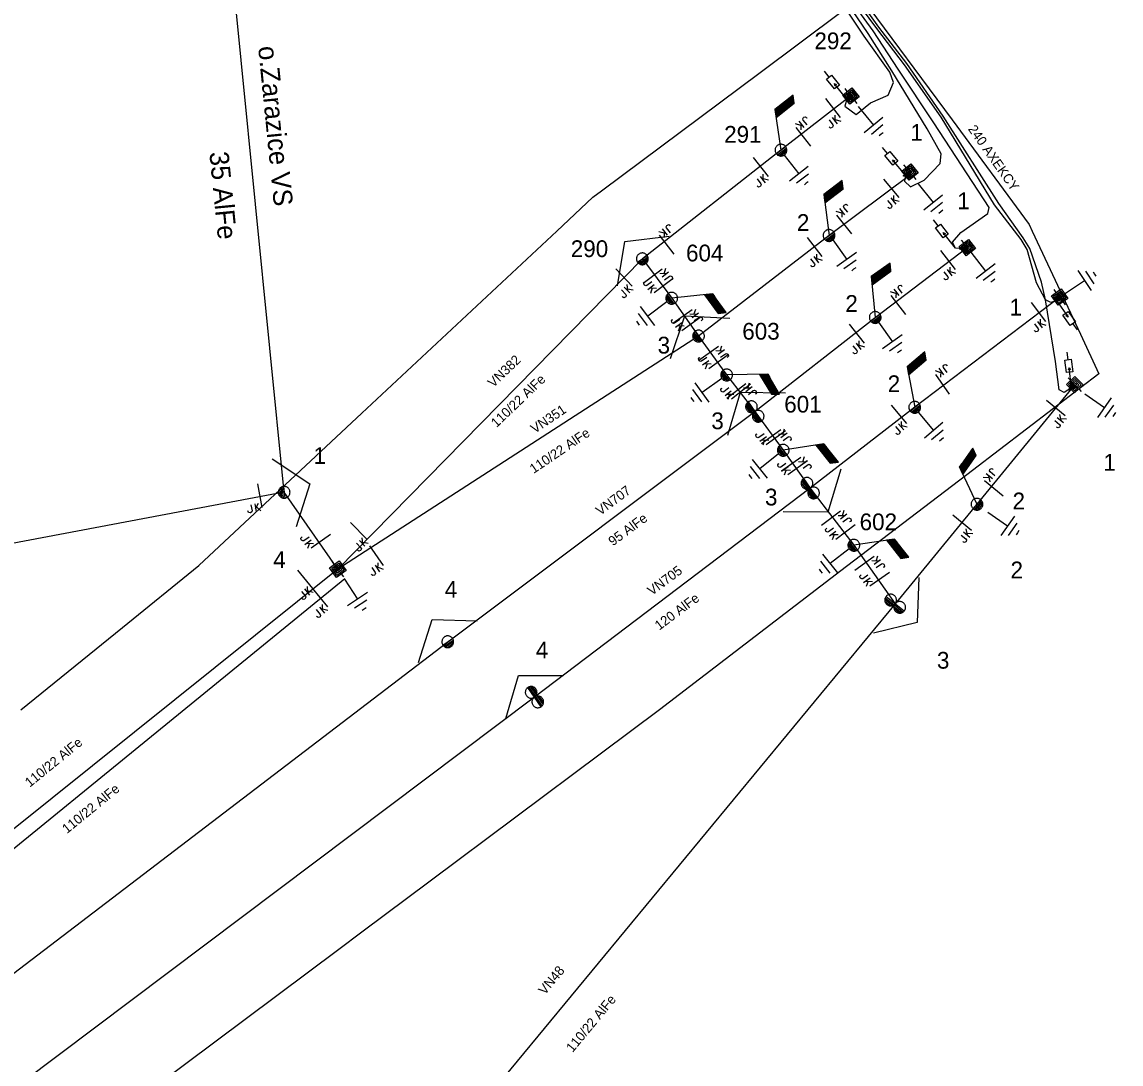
# Model space of a CAD drawing. Extents: x -545588 to -543214, y -1196037 to -1194452.
# Drawn here: x -545323 to -545208.3, y -1195024.5 to -1194915.7 of the extents above; entities that cross this region are included whole.
import ezdxf

# ---------------------------------------------------------------- set-up
doc = ezdxf.new("R2010")
doc.units = 0
for name, color, linetype in [('DOPLŇ_POPISY', 7, 'Continuous'), ('ELE_EON', 7, 'Continuous'), ('ELE_EON_POPIS', 7, 'Continuous'), ('Implicitní', 7, 'Continuous'), ('KONEC_VEDENÍ', 7, 'Continuous'), ('POL_ZNAČKA_PRACOVNÍ', 7, 'Continuous'), ('POL_ČÍSLO_PRACOVNÍ', 7, 'Continuous'), ('SDEL_EON', 7, 'Continuous'), ('SDEL_EON_POPIS', 7, 'Continuous'), ('TECH_OCHR_PÁSMO_HRAN', 7, 'Continuous'), ('Vrstva 18', 7, 'Continuous'), ('Vrstva 19', 7, 'Continuous'), ('Vrstva 35', 7, 'Continuous'), ('Vrstva 52', 7, 'Continuous'), ('Vrstva 53', 7, 'Continuous'), ('Vrstva 54', 7, 'Continuous'), ('ZP_EON', 7, 'Continuous'), ('ZP_EON_POPIS', 7, 'Continuous')]:
    doc.layers.add(name, color=color, linetype=linetype)

# ---------------------------------------------------------------- blocks, each defined once
blk = doc.blocks.new('VN840')
at = {"layer": 'POL_ZNAČKA_PRACOVNÍ'}
for points in [[(-0.01, 1.41), (-0.01, -1.09)], [(-1.51, -1.24), (-1.51, -1.15)], [(-1.09, -0.59), (-1.09, -1.24)], [(-0.68, -0.59), (-0.68, -1.42)], [(-0.68, -1.11), (-0.27, -0.59)], [(-0.54, -0.94), (-0.2, -1.42)], [(-1.48, -1.35), (-1.51, -1.24)], [(-1.33, -1.42), (-1.48, -1.35)], [(-1.27, -1.42), (-1.33, -1.42)], [(-1.13, -1.35), (-1.27, -1.42)], [(-1.09, -1.24), (-1.13, -1.35)]]:
    blk.add_lwpolyline(points, dxfattribs=at)
blk = doc.blocks.new('VN860')
at = {"layer": 'POL_ZNAČKA_PRACOVNÍ'}
for points in [[(-3.74, 0), (0.01, 2.82)], [(0.01, 2.82), (3.76, 0)]]:
    blk.add_lwpolyline(points, dxfattribs=at)
blk = doc.blocks.new('VN440')
at = {"layer": 'ELE_EON_POPIS'}
for points in [[(1.22, 0), (1.21, 0.13), (1.19, 0.25), (1.16, 0.38), (1.11, 0.5), (1.05, 0.61), (0.98, 0.72), (0.9, 0.82), (0.81, 0.91), (0.71, 0.99), (0.6, 1.06), (0.49, 1.12), (0.37, 1.16), (0.25, 1.2), (0.12, 1.22), (-0.01, 1.22), (-0.14, 1.22), (-0.26, 1.2), (-0.39, 1.16), (-0.51, 1.12), (-0.62, 1.06), (-0.73, 0.99), (-0.83, 0.91), (-0.92, 0.82), (-1, 0.72), (-1.07, 0.61), (-1.13, 0.5), (-1.18, 0.38), (-1.21, 0.25), (-1.23, 0.13), (-1.24, 0), (-1.23, -0.13), (-1.21, -0.26), (-1.18, -0.38), (-1.13, -0.5), (-1.07, -0.62), (-1, -0.73), (-0.92, -0.83), (-0.83, -0.92), (-0.73, -1), (-0.62, -1.07), (-0.51, -1.13), (-0.39, -1.17), (-0.26, -1.2), (-0.14, -1.23), (-0.01, -1.23), (0.12, -1.23), (0.25, -1.2), (0.37, -1.17), (0.49, -1.13), (0.6, -1.07), (0.71, -1), (0.81, -0.92), (0.9, -0.83), (0.98, -0.73), (1.05, -0.62), (1.11, -0.5), (1.16, -0.38), (1.19, -0.26), (1.21, -0.13), (1.22, 0)], [(-1.24, 0), (1.22, 0)], [(-1.18, -0.34), (1.1, -0.34)], [(-1.01, -0.63), (0.97, -0.63)], [(-0.74, -0.92), (0.68, -0.92)]]:
    blk.add_lwpolyline(points, dxfattribs=at)
blk = doc.blocks.new('VN890')
at = {"layer": 'SDEL_EON_POPIS'}
for points in [[(-0.41, 0.41), (0.41, 0)], [(-0.41, -0.41), (-0.41, 0.41)], [(0.41, 0), (-0.41, -0.41)], [(-0.34, 0.31), (0.27, 0), (-0.34, -0.3), (-0.34, 0.31)], [(-0.26, 0.2), (0.1, 0), (-0.26, -0.18), (-0.26, 0.2)], [(-0.19, 0.09), (-0.04, 0), (-0.19, -0.08), (-0.19, 0.09)], [(-0.16, -0.01), (-0.16, 0.03), (-0.13, 0.01), (-0.16, -0.01)]]:
    blk.add_lwpolyline(points, dxfattribs=at)
blk = doc.blocks.new('VN820')
at = {"layer": 'DOPLŇ_POPISY'}
for points in [[(0, 0), (0, -2.1)], [(-0.32, -1.63), (0.34, -1.63)], [(-0.32, -2.95), (-0.32, -1.63)], [(0, -2.1), (-0.12, -1.86)], [(0, -2.1), (0.12, -1.86)], [(0.34, -1.63), (0.34, -2.95)], [(0.34, -2.95), (-0.32, -2.95)], [(0, -2.95), (0, -3.75)]]:
    blk.add_lwpolyline(points, dxfattribs=at)
blk = doc.blocks.new('VN810')
at = {"layer": 'POL_ZNAČKA_PRACOVNÍ'}
for points in [[(0, -1.25), (0, -3.75)], [(1.25, -3.75), (-1.25, -3.75)], [(0.77, -4.37), (-0.8, -4.37)], [(0, -5), (-0.25, -5)], [(0.27, -5), (0, -5)]]:
    blk.add_lwpolyline(points, dxfattribs=at)
blk = doc.blocks.new('VN450')
at = {"layer": 'ELE_EON_POPIS'}
for points in [[(0, 0), (-0.01, 0.13), (-0.03, 0.25), (-0.06, 0.38), (-0.11, 0.5), (-0.16, 0.61), (-0.23, 0.72), (-0.31, 0.82), (-0.4, 0.91), (-0.5, 0.99), (-0.61, 1.06), (-0.72, 1.11), (-0.84, 1.16), (-0.97, 1.19), (-1.09, 1.21), (-1.22, 1.22), (-1.35, 1.21), (-1.47, 1.19), (-1.59, 1.16), (-1.71, 1.11), (-1.83, 1.06), (-1.93, 0.99), (-2.03, 0.91), (-2.12, 0.82), (-2.2, 0.72), (-2.27, 0.61), (-2.33, 0.5), (-2.38, 0.38), (-2.41, 0.25), (-2.43, 0.13), (-2.44, 0), (-2.43, -0.13), (-2.41, -0.25), (-2.38, -0.38), (-2.33, -0.5), (-2.27, -0.61), (-2.2, -0.72), (-2.12, -0.82), (-2.03, -0.91), (-1.93, -0.99), (-1.83, -1.06), (-1.71, -1.11), (-1.59, -1.16), (-1.47, -1.19), (-1.35, -1.21), (-1.22, -1.22), (-1.09, -1.21), (-0.97, -1.19), (-0.84, -1.16), (-0.72, -1.11), (-0.61, -1.06), (-0.5, -0.99), (-0.4, -0.91), (-0.31, -0.82), (-0.23, -0.72), (-0.16, -0.61), (-0.11, -0.5), (-0.06, -0.38), (-0.03, -0.25), (-0.01, -0.13), (0, 0)], [(-2.44, 0), (2.44, 0)], [(2.44, 0), (2.43, 0.13), (2.41, 0.25), (2.38, 0.38), (2.33, 0.5), (2.27, 0.61), (2.2, 0.72), (2.12, 0.82), (2.03, 0.91), (1.94, 0.99), (1.83, 1.06), (1.71, 1.11), (1.6, 1.16), (1.47, 1.19), (1.35, 1.21), (1.22, 1.22), (1.09, 1.21), (0.97, 1.19), (0.84, 1.16), (0.72, 1.11), (0.61, 1.06), (0.5, 0.99), (0.4, 0.91), (0.31, 0.82), (0.23, 0.72), (0.16, 0.61), (0.11, 0.5), (0.06, 0.38), (0.03, 0.25), (0.01, 0.13), (0, 0), (0.01, -0.13), (0.03, -0.25), (0.06, -0.38), (0.11, -0.5), (0.16, -0.61), (0.23, -0.72), (0.31, -0.82), (0.4, -0.91), (0.5, -0.99), (0.61, -1.06), (0.72, -1.11), (0.84, -1.16), (0.97, -1.19), (1.09, -1.21), (1.22, -1.22), (1.35, -1.21), (1.47, -1.19), (1.6, -1.16), (1.71, -1.11), (1.83, -1.06), (1.94, -0.99), (2.03, -0.91), (2.12, -0.82), (2.2, -0.72), (2.27, -0.61), (2.33, -0.5), (2.38, -0.38), (2.41, -0.25), (2.43, -0.13), (2.44, 0)], [(-2.4, -0.31), (-0.04, -0.31)], [(-2.26, -0.61), (-0.17, -0.61)], [(-2.01, -0.92), (-0.42, -0.92)], [(0.04, -0.31), (2.4, -0.31)], [(0.17, -0.61), (2.27, -0.61)], [(0.42, -0.92), (2.02, -0.92)]]:
    blk.add_lwpolyline(points, dxfattribs=at)
blk = doc.blocks.new('VN001')
at = {"layer": 'Implicitní'}
for p, q in [((1.99, 3.48), (4.4, 3.48)), ((2.02, 3.53), (4.43, 3.53)), ((2.05, 3.58), (4.46, 3.58)), ((2.07, 3.63), (4.49, 3.63)), ((2.1, 3.68), (4.52, 3.68)), ((2.13, 3.73), (2.54, 3.73)), ((1.73, 3.03), (4.14, 3.03)), ((1.76, 3.08), (4.17, 3.08)), ((1.79, 3.13), (4.2, 3.13)), ((1.82, 3.18), (4.23, 3.18)), ((1.85, 3.23), (4.26, 3.23)), ((1.87, 3.28), (4.29, 3.28)), ((1.9, 3.33), (4.32, 3.33)), ((1.93, 3.38), (4.35, 3.38)), ((1.96, 3.43), (4.37, 3.43))]:
    blk.add_line(p, q, dxfattribs=at)
blk.add_lwpolyline([(2.13, 3.73), (0, 0)], dxfattribs=at)
blk.add_lwpolyline([(4.55, 3.73), (2.13, 3.73), (1.7, 2.98), (4.12, 2.99)], close=True, dxfattribs=at)
blk = doc.blocks.new('VN470')
at = {"layer": 'ELE_EON_POPIS'}
for points in [[(-1.23, 1.22), (1.23, 1.22)], [(-1.23, -1.23), (-1.23, 1.22)], [(-0.92, 0.9), (0.92, 0.9)], [(-0.92, -0.95), (-0.92, 0.9)], [(-0.61, 0.61), (0.61, 0.61)], [(-0.61, -0.62), (-0.61, 0.61)], [(-0.31, -0.27), (-0.31, 0.34)], [(-0.31, 0.34), (0.31, 0.34)], [(0, 1.22), (0, 1.97)], [(0.31, 0.34), (0.31, -0.27)], [(0.61, 0.61), (0.61, -0.62)], [(0.92, 0.9), (0.92, -0.95)], [(1.23, 1.22), (1.23, -1.23)], [(1.23, -1.23), (-1.23, -1.23)], [(0.92, -0.95), (-0.92, -0.95)], [(0.61, -0.62), (-0.61, -0.62)], [(0.31, -0.27), (-0.31, -0.27)], [(0, -1.23), (0, -1.98)]]:
    blk.add_lwpolyline(points, dxfattribs=at)

msp = doc.modelspace()

# ---------------------------------------------------------------- linework, layer by layer
at = {"layer": 'ELE_EON'}
for points in [[(-545236.46, -1194923.4), (-545243.76, -1194929.05)], [(-545243.76, -1194929.05), (-545258.23, -1194940.4)], [(-545230.22, -1194931.6), (-545238.74, -1194937.96)], [(-545238.74, -1194937.96), (-545252.36, -1194948.47)], [(-545233.92, -1194946.52), (-545224.31, -1194939.23)], [(-545258.23, -1194940.4), (-545290.02, -1194972.8)], [(-545214.67, -1194944.4), (-545229.8, -1194955.9)], [(-545246.49, -1194956.34), (-545233.92, -1194946.52)], [(-545252.36, -1194948.47), (-545290.02, -1194972.8)], [(-545213.1, -1194953.54), (-545223.3, -1194966.03)], [(-545395.75, -1195077.92), (-545332.4, -1195021.48), (-545278.54, -1194980.38), (-545246.49, -1194956.34)], [(-545229.8, -1194955.9), (-545240.7, -1194964.34)], [(-545240.7, -1194964.34), (-545269.49, -1194986.16), (-545326.84, -1195029.29), (-545358.05, -1195052.83)], [(-545223.3, -1194966.03), (-545231.84, -1194976.41)], [(-545290.02, -1194972.8), (-545405.11, -1195065.07), (-545495.54, -1195139.14), (-545571.44, -1195160.65)], [(-545289.27, -1194973.82), (-545403.67, -1195067.08), (-545494.32, -1195141.28), (-545571.32, -1195163.18)], [(-545231.84, -1194976.41), (-545288.22, -1195044.64), (-545343.3, -1195111.41), (-545397.6, -1195177.04), (-545441.95, -1195249.1), (-545485.78, -1195319.69), (-545525.23, -1195383.69), (-545557.58, -1195435.71)]]:
    msp.add_lwpolyline(points, dxfattribs=at)
at = {"layer": 'Vrstva 35'}
for points in [[(-545235.38, -1194913.06), (-545225.9, -1194925.9), (-545217.85, -1194936.81), (-545217.53, -1194937.5), (-545215.93, -1194940.93), (-545212.5, -1194948.28), (-545210.58, -1194952.4), (-545212.5, -1194953.87), (-545223.78, -1194962.5), (-545237.5, -1194972.99), (-545256.45, -1194987.5), (-545262.5, -1194992.01), (-545280.38, -1195005.38), (-545287.5, -1195010.7), (-545289.91, -1195012.5), (-545312.5, -1195029.39)], [(-545323.09, -1194987.5), (-545312.5, -1194978.9), (-545304.54, -1194972.43), (-545293.92, -1194962.5), (-545287.5, -1194956.5), (-545267.17, -1194937.5), (-545263.39, -1194933.97), (-545262.5, -1194933.31), (-545245.95, -1194920.95), (-545237.5, -1194914.64)]]:
    msp.add_lwpolyline(points, dxfattribs=at)
at = {"layer": 'Vrstva 52'}
for points in [[(-545295.62, -1194964.78), (-545301.62, -1194904.6), (-545301.79, -1194902.92), (-545302.62, -1194901.45), (-545318.54, -1194873.42)], [(-545258.23, -1194940.4), (-545255.17, -1194944.52)], [(-545255.17, -1194944.52), (-545252.36, -1194948.47)], [(-545252.36, -1194948.47), (-545249.44, -1194952.53)], [(-545249.44, -1194952.53), (-545246.49, -1194956.34)], [(-545246.49, -1194956.34), (-545243.52, -1194960.39)], [(-545243.52, -1194960.39), (-545240.53, -1194964.58)], [(-545295.62, -1194964.78), (-545381.37, -1194980.94), (-545453.74, -1194986.07), (-545493.42, -1194989.16)], [(-545290.02, -1194972.8), (-545295.62, -1194964.78)], [(-545240.53, -1194964.58), (-545236.15, -1194970.31)], [(-545236.15, -1194970.31), (-545231.84, -1194976.41)]]:
    msp.add_lwpolyline(points, dxfattribs=at)
at = {"layer": 'ZP_EON'}
for points in [[(-545236.49, -1194923.55), (-545236.72, -1194923.58), (-545236.89, -1194923.73), (-545237.09, -1194924.48), (-545235.92, -1194925.33), (-545234.43, -1194924.11), (-545232.58, -1194923.3), (-545232.02, -1194922.01), (-545232.39, -1194920.91), (-545235.07, -1194917.17), (-545239.41, -1194910.6)], [(-545230.31, -1194931.31), (-545230.78, -1194931.68), (-545230.78, -1194931.68), (-545230.86, -1194932.28), (-545230.25, -1194932.87), (-545228.8, -1194932.18), (-545227.16, -1194930.44), (-545227.04, -1194929.44), (-545228.49, -1194926.82), (-545232.2, -1194920.78), (-545234.65, -1194916.87), (-545239.05, -1194910.4)], [(-545224.18, -1194939.38), (-545224.73, -1194939.37), (-545225.56, -1194939.3), (-545225.86, -1194938.67), (-545224.97, -1194937.65), (-545222.16, -1194935.67), (-545222.02, -1194935.04), (-545227.82, -1194926.2), (-545231.53, -1194920.6), (-545234.13, -1194916.6), (-545238.74, -1194910.26)], [(-545214.51, -1194944.61), (-545214.64, -1194944.43), (-545214.85, -1194944.63), (-545215, -1194944.76), (-545215.59, -1194944.96), (-545216.14, -1194944.67), (-545217.09, -1194942.9), (-545218.06, -1194939.43), (-545218.69, -1194938.4), (-545221.46, -1194934.77), (-545227.03, -1194925.62), (-545230.86, -1194920.16), (-545233.75, -1194916.35), (-545238.35, -1194910.11)], [(-545213.08, -1194953.79), (-545213.42, -1194953.86), (-545214.2, -1194954.37), (-545214.73, -1194954.07), (-545215.11, -1194951.12), (-545216.14, -1194944.67), (-545216.55, -1194942.85), (-545217.78, -1194939.34), (-545218.48, -1194938.21), (-545221.01, -1194934.62), (-545226.84, -1194925.51), (-545230.61, -1194920), (-545233.55, -1194916.21), (-545237.86, -1194910.11)]]:
    msp.add_lwpolyline(points, dxfattribs=at)

# ---------------------------------------------------------------- block references
at = {"layer": 'DOPLŇ_POPISY'}
for name, p, xscale, yscale, rotation in [('VN470', (-545236.46, -1194923.4), 0.5000000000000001, 0.5, 38.57166112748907), ('VN440', (-545243.76, -1194929.05), 0.5, 0.5, 38.18600550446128), ('VN470', (-545230.3, -1194931.34), 0.5, 0.5000000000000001, 39.025683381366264), ('VN440', (-545238.74, -1194937.96), 0.5, 0.49999999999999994, 34.95319163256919), ('VN470', (-545224.31, -1194939.23), 0.5, 0.5000000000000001, 37.661386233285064), ('VN440', (-545258.23, -1194940.4), 0.5, 0.5, 35.95226383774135), ('VN440', (-545255.16, -1194944.52), 0.5, 0.5, -53.39277781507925), ('VN470', (-545214.67, -1194944.4), 0.5, 0.5, 35.09740273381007), ('VN440', (-545233.92, -1194946.52), 0.5, 0.5000000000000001, 35.223016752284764), ('VN440', (-545252.36, -1194948.47), 0.5, 0.5, -54.047736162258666), ('VN440', (-545249.43, -1194952.53), 0.5, 0.5, -54.273602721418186), ('VN470', (-545213.1, -1194953.54), 0.5, 0.49999999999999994, 43.663602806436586), ('VN450', (-545246.49, -1194956.34), 0.5000000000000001, 0.4999999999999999, -54.77698328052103), ('VN440', (-545229.8, -1194955.9), 0.5, 0.5, 40.44745010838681), ('VN440', (-545243.52, -1194960.39), 0.5, 0.49999999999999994, -51.362411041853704), ('VN450', (-545240.7, -1194964.34), 0.5000000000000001, 0.5, -55.28859164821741), ('VN440', (-545295.62, -1194964.78), 0.5, 0.5, -84.30825828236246), ('VN440', (-545223.3, -1194966.02), 0.5, 0.5, 50.71019441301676), ('VN440', (-545236.15, -1194970.31), 0.5, 0.5, -54.644949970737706), ('VN470', (-545290.02, -1194972.8), 0.5, 0.5, 35.95226383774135), ('VN450', (-545231.84, -1194976.41), 0.5, 0.4999999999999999, -38.48263617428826), ('VN440', (-545278.54, -1194980.38), 0.49999999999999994, 0.5000000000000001, 35.22301664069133), ('VN450', (-545269.49, -1194986.16), 0.49999999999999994, 0.5, 124.71140827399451)]:
    msp.add_blockref(name, p, dxfattribs=dict(at, xscale=xscale, yscale=yscale, rotation=rotation))
at = {"layer": 'POL_ZNAČKA_PRACOVNÍ'}
for p, rotation in [((-545236.49, -1194923.55), 39.57557080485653), ((-545244.21, -1194928.59), 38.18696673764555), ((-545230.22, -1194931.6), 38.759191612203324), ((-545239.06, -1194937.41), 35.223016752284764), ((-545224.7, -1194938.73), 37.66631396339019), ((-545215.21, -1194944.74), 123.37775649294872), ((-545254.66, -1194944.14), -53.40005286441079), ((-545234.29, -1194946), 35.223016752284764), ((-545248.93, -1194952.16), -54.27577217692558), ((-545213.08, -1194953.79), 55.019999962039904), ((-545230.26, -1194955.46), 40.4480305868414), ((-545243.03, -1194959.99), -51.35691383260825), ((-545223.18, -1194966.13), 55.0153639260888), ((-545235.68, -1194969.89), -51.52944450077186), ((-545290.02, -1194972.8), 33.3588583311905)]:
    msp.add_blockref('VN810', p, dxfattribs=dict(at, rotation=rotation))
at = {"layer": 'POL_ČÍSLO_PRACOVNÍ'}
for p, rotation in [((-545236.89, -1194923.73), -141.52061114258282), ((-545230.78, -1194931.68), -140.71454174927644), ((-545225.56, -1194939.3), -142.37886389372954), ((-545215, -1194944.76), 35.09724162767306), ((-545213.42, -1194953.86), -172.82982508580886)]:
    msp.add_blockref('VN820', p, dxfattribs=dict(at, rotation=rotation))
at = {"layer": 'TECH_OCHR_PÁSMO_HRAN'}
for p, rotation in [((-545243.76, -1194929.05), 38.18679450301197), ((-545238.74, -1194937.96), 37.17218889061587), ((-545233.92, -1194946.52), 35.223016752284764), ((-545255.17, -1194944.52), -54.047736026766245), ((-545229.8, -1194955.9), 40.44745010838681), ((-545249.44, -1194952.53), -59.175191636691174), ((-545243.52, -1194960.39), -51.362411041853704), ((-545223.3, -1194966.03), 55.0153638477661), ((-545236.15, -1194970.31), -51.52944450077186)]:
    msp.add_blockref('VN001', p, dxfattribs=dict(at, rotation=rotation))
at = {"layer": 'Vrstva 18'}
for name, p, rotation in [('VN840', (-545238.24, -1194924.77), 37.809900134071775), ('VN840', (-545241.52, -1194927.56), -141.42955829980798), ('VN840', (-545245.77, -1194930.93), 38.18633062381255), ('VN840', (-545232.15, -1194933.16), 39.020663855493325), ('VN840', (-545237.25, -1194936.69), -140.97279439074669), ('VN860', (-545258.13, -1194940.65), 43.75872502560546), ('VN840', (-545255.79, -1194938.81), -141.81291385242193), ('VN840', (-545240.15, -1194939.28), 37.16967780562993), ('VN840', (-545226.25, -1194940.64), 37.484938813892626), ('VN840', (-545260.03, -1194942.47), 43.759150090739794), ('VN840', (-545257.04, -1194942.09), 127.11686113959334), ('VN840', (-545256.12, -1194943.31), -52.88313888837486), ('VN840', (-545231.61, -1194945.11), -142.3361888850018), ('VN860', (-545252.21, -1194948.71), 34.11712501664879), ('VN840', (-545253.22, -1194947.29), -54.55751941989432), ('VN840', (-545253.92, -1194946.31), 125.44248060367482), ('VN840', (-545216.8, -1194946.07), 37.15255827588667), ('VN840', (-545235.76, -1194948.34), 38.29414440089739), ('VN840', (-545250.4, -1194951.25), -54.52896109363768), ('VN840', (-545251.19, -1194950.14), 125.47103896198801), ('VN860', (-545246.31, -1194956.61), 36.40879723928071), ('VN840', (-545248.06, -1194954.38), -51.92876399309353), ('VN840', (-545226.98, -1194953.38), -144.89947772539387), ('VN840', (-545248.3, -1194954.07), 128.07123606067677), ('VN840', (-545231.35, -1194956.75), 40.44653339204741), ('VN840', (-545214.94, -1194956.06), 50.7004805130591), ('VN840', (-545244.41, -1194959.19), -53.56914167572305), ('VN840', (-545244.66, -1194958.85), 126.430858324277), ('VN860', (-545295.62, -1194964.82), -70.65378887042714), ('VN840', (-545242.14, -1194962.33), -54.48819997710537), ('VN840', (-545242.57, -1194961.72), 125.51179994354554), ('VN860', (-545240.53, -1194964.58), -143.3872638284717), ('VN840', (-545221.67, -1194964.28), -129.2995194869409), ('VN840', (-545298.13, -1194965.29), 10.64668321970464), ('VN840', (-545238.42, -1194967.36), 127.18888063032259), ('VN840', (-545237.15, -1194969.04), -52.811119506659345), ('VN840', (-545224.72, -1194968.02), 50.71059436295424), ('VN840', (-545291.91, -1194970), -54.584030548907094), ('VN840', (-545287.69, -1194968.92), 44.07588337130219), ('VN840', (-545285.91, -1194971.51), 34.4793945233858), ('VN840', (-545234.92, -1194972.07), 125.29263057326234), ('VN840', (-545293.33, -1194973.98), 39.18124444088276), ('VN840', (-545233.58, -1194973.97), -54.70736942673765), ('VN860', (-545231.73, -1194976.58), -129.28824718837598), ('VN840', (-545291.79, -1194975.87), 39.189741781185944), ('VN860', (-545278.54, -1194980.38), 35.22301664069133), ('VN860', (-545269.49, -1194986.16), 36.89043607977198)]:
    msp.add_blockref(name, p, dxfattribs=dict(at, rotation=rotation))
at = {"layer": 'Vrstva 19'}
for p, rotation in [((-545236.72, -1194923.58), -141.34019170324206), ((-545230.61, -1194931.66), -171.49811939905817), ((-545224.73, -1194939.37), 178.8509611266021), ((-545214.85, -1194944.63), -137.48955276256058), ((-545213.42, -1194953.86), -134.2361027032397)]:
    msp.add_blockref('VN890', p, dxfattribs=dict(at, rotation=rotation))

# ---------------------------------------------------------------- texts
at = {"layer": 'ELE_EON_POPIS'}
for s, rotation, p in [('110/22 AlFe', 43.759, (-545273.46, -1194958.08)), ('110/22 AlFe', 34.117, (-545269.57, -1194962.86)), ('95 AlFe', 36.409, (-545261.31, -1194970.43)), ('120 AlFe', 36.692, (-545256.47, -1194979.23)), ('110/22 AlFe', 39.181, (-545322.17, -1194995.62)), ('110/22 AlFe', 39.19, (-545318.29, -1195000.46)), ('110/22 AlFe', 50.365, (-545265.51, -1195023.32))]:
    msp.add_text(s, height=1, rotation=rotation, dxfattribs=at).set_placement(p)
at = {"layer": 'KONEC_VEDENÍ'}
for s, p in [('2', (-545219.59, -1194966.56)), ('602', (-545235.55, -1194968.74))]:
    msp.add_text(s, height=1.75, dxfattribs=at).set_placement(p)
at = {"layer": 'POL_ZNAČKA_PRACOVNÍ'}
for s, p in [('292', (-545240.27, -1194918.52)), ('291', (-545249.69, -1194928.28)), ('1', (-545230.25, -1194928.08)), ('1', (-545225.36, -1194935.22)), ('2', (-545242.1, -1194937.49)), ('290', (-545265.7, -1194940.22)), ('604', (-545253.67, -1194940.67)), ('2', (-545237.04, -1194945.94)), ('1', (-545219.91, -1194946.32)), ('603', (-545247.8, -1194948.84)), ('3', (-545256.64, -1194950.29)), ('2', (-545232.62, -1194954.32)), ('601', (-545243.42, -1194956.45)), ('3', (-545251.03, -1194958.19)), ('1', (-545292.56, -1194961.82)), ('1', (-545210.11, -1194962.53)), ('3', (-545245.43, -1194966.15)), ('4', (-545296.76, -1194972.68)), ('2', (-545219.8, -1194973.76)), ('4', (-545278.85, -1194975.78)), ('4', (-545269.35, -1194982.11)), ('3', (-545227.48, -1194983.19))]:
    msp.add_text(s, height=1.75, dxfattribs=at).set_placement(p)
at = {"layer": 'SDEL_EON'}
for s, rotation, p in [('VN382', 43.759, (-545273.79, -1194953.9)), ('VN351', 34.117, (-545269.46, -1194958.68)), ('VN707', 36.409, (-545262.63, -1194967.24)), ('VN705', 36.692, (-545257.24, -1194975.6)), ('VN48', 50.365, (-545268.41, -1195017.32))]:
    msp.add_text(s, height=1, rotation=rotation, dxfattribs=at).set_placement(p)
at = {"layer": 'Vrstva 53'}
msp.add_text('35 AlFe', height=2, rotation=275.692, dxfattribs=at).set_placement((-545303.43, -1194929.29))
at = {"layer": 'Vrstva 54'}
msp.add_text('o.Zarazice VS', height=2, rotation=275.692, dxfattribs=at).set_placement((-545298.34, -1194918.27))
at = {"layer": 'ZP_EON_POPIS'}
msp.add_text('240 AXEKCY', height=1, rotation=305.174, dxfattribs=at).set_placement((-545224.28, -1194926.86))

doc.saveas('drawing.dxf')
